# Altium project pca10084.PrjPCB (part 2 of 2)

## Sheet pca10084_sheet7_power_supply.SchDoc: PCA10084 - Power Supply
size A3; Organization: Nordic Semiconductor; DocumentNumber: 7; Revision: 0.7.0; SheetNumber: 7; SheetTotal: 8; Author: GETR; CompanyName: Nordic Semiconductor; DrawnBy: GETR
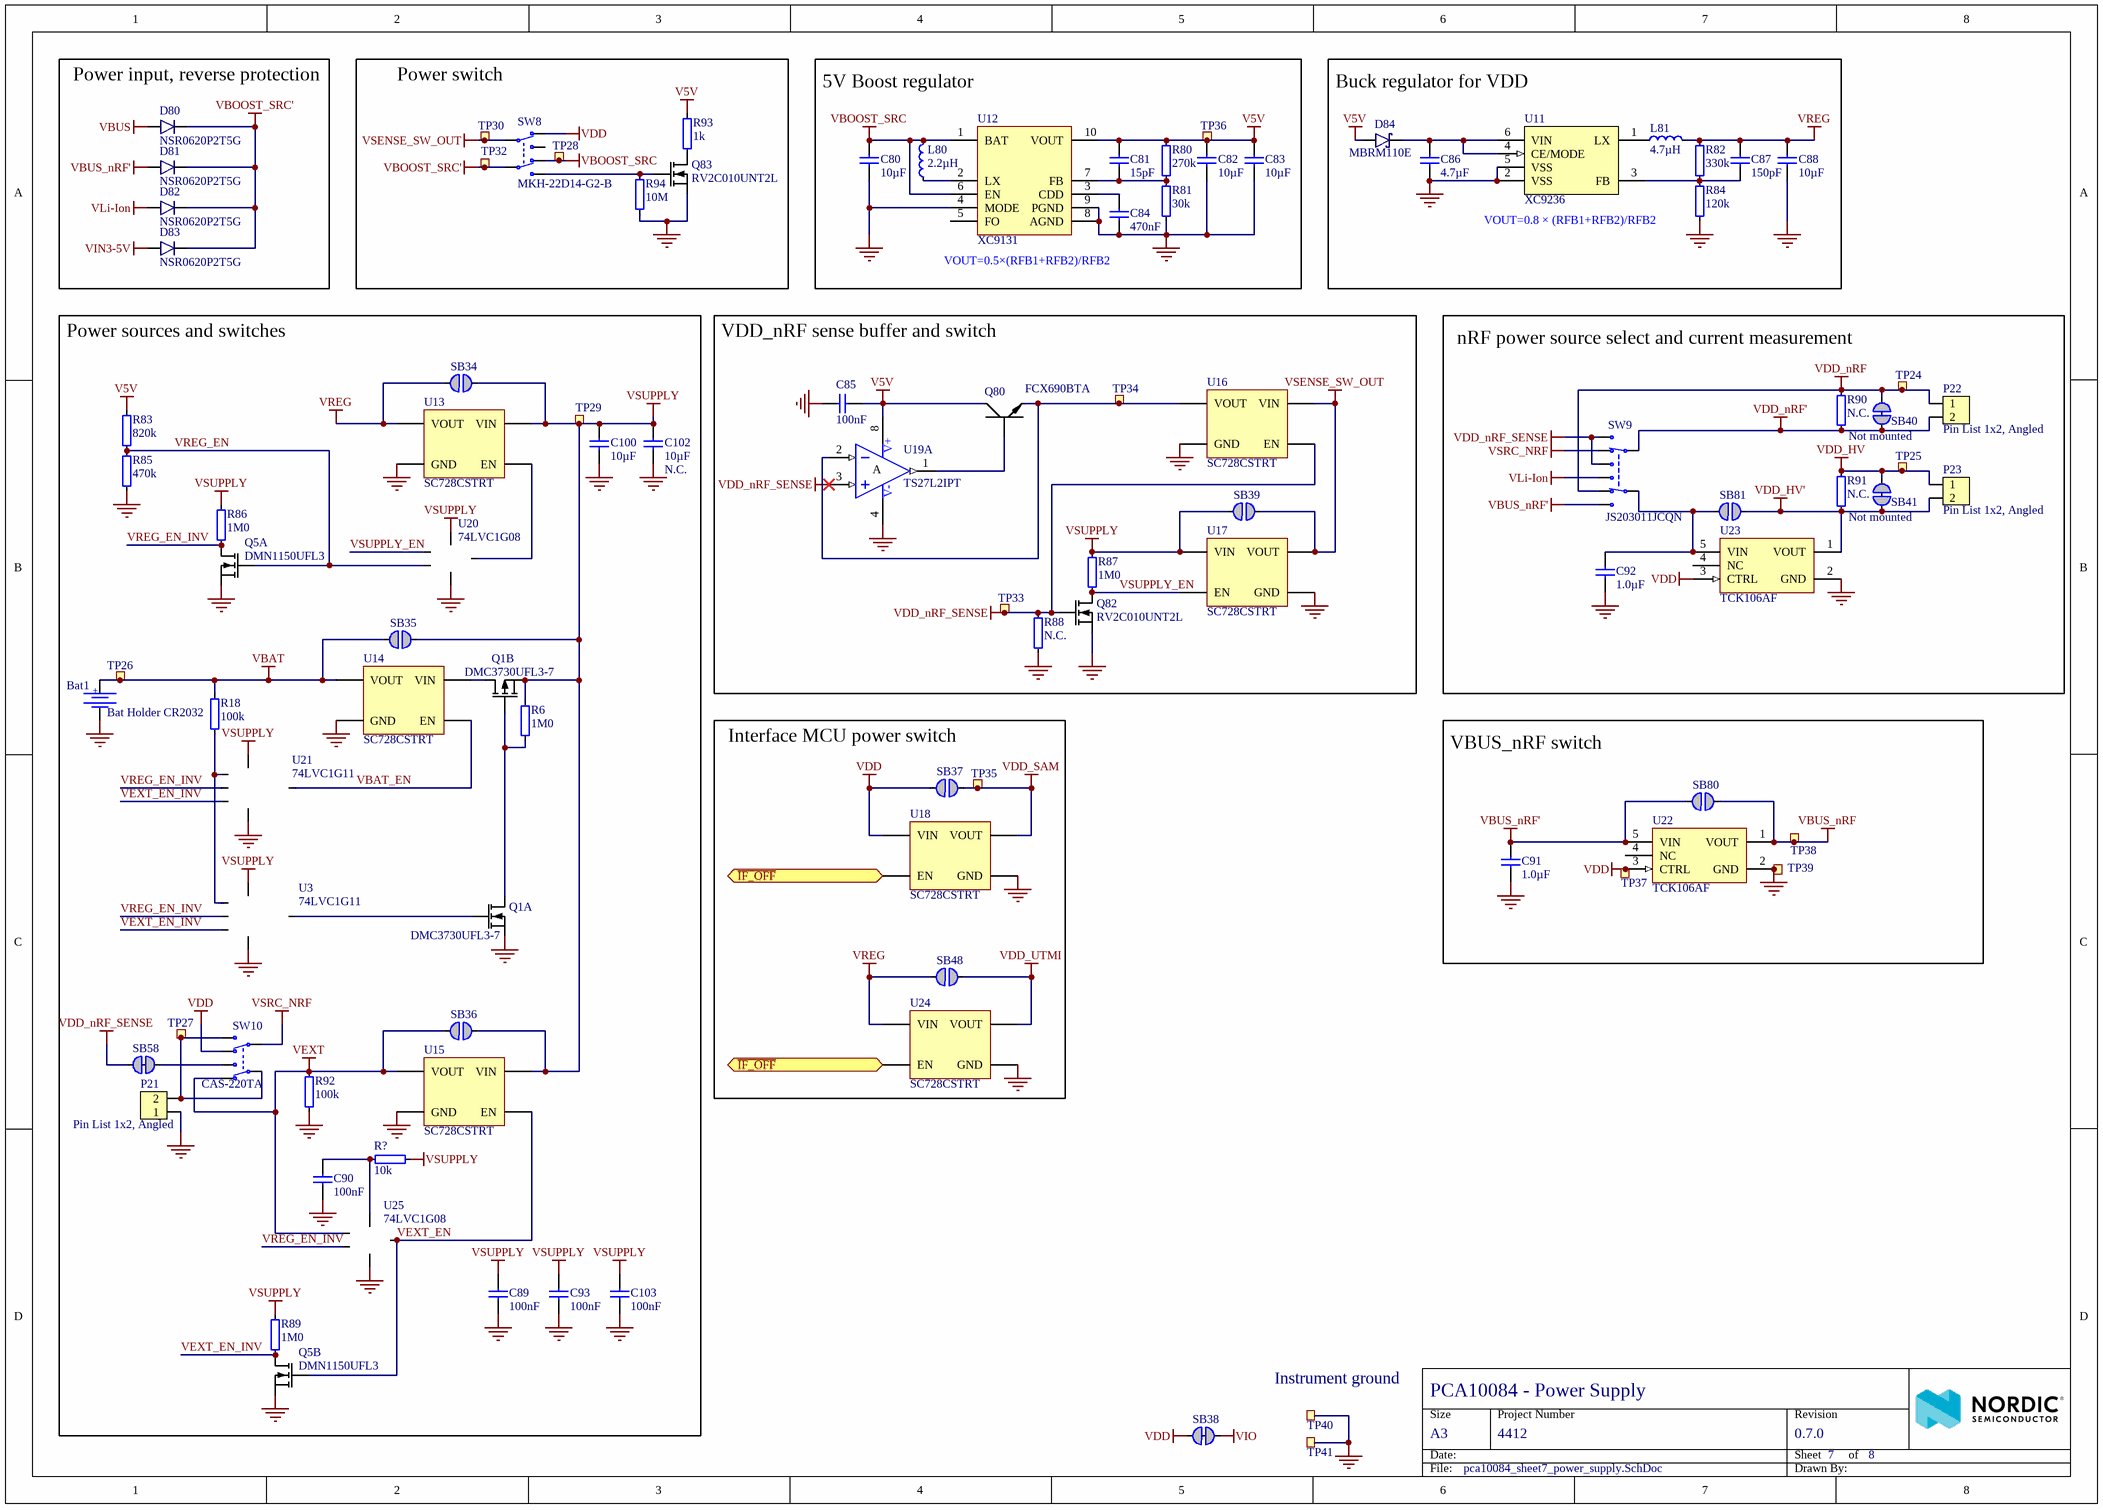
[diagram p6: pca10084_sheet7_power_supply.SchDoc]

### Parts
Bat1  Bat Holder CR2032  [CR2032_HOLDER_SMD]
C80  10µF  [CAPC1608X06L]
C81  15pF  [CAPC1005X04L]
C82  10µF  [CAPC1608X06L]
C83  10µF  [CAPC1608X06L]
C84  470nF  [CAPC1005X04L]
C85  100nF  [CAPC1005X04L]
C86  4.7µF  [CAPC2012X11L]
C87  150pF  [CAPC1005X04L]
C88  10µF  [CAPC1608X06L]
C89  100nF  [CAPC0603X03L_C]
C90  100nF  [CAPC0603X03L_C]
C91  1.0µF  [CAPC1608X06L]
C92  1.0µF  [CAPC1608X06L]
C93  100nF  [CAPC0603X03L_C]
C100  10µF  [CAPC1608X06L]
C102  10µF  Assembly: N.C.  [CAPC1608X06L]
C103  100nF  [CAPC0603X03L_C]
D80  NSR0620P2T5G  [SODFL100X40-2N]
D81  NSR0620P2T5G  [SODFL100X40-2N]
D82  NSR0620P2T5G  [SODFL100X40-2N]
D83  NSR0620P2T5G  [SODFL100X40-2N]
D84  MBRM110E  [DO-216AA]
L80  2.2µH  [TY-NR3015]
L81  4.7µH  [TY-NR3015]
P21  Pin List 1x2, Angled  [LIST_ANG_1x2-SMD-2.54MM]
P22  Pin List 1x2, Angled  [LIST_ANG_1x2-SMD-2.54MM]
P23  Pin List 1x2, Angled  [LIST_ANG_1x2-SMD-2.54MM]
Q1  DMC3730UFL3-7  [DMC3730UFL3-7]  (parts A,B of 2)
Q5  DMN1150UFL3  [X2DFN35P100X130X35-6N]  (parts A,B of 2)
Q80  FCX690BTA  [SOT89-150P409X160-3N]
Q82  RV2C010UNT2L  [DFN65P100X40-3L]
Q83  RV2C010UNT2L  [DFN65P100X40-3L]
R6  1M0  [RESC0603X03L_C]
R18  100k  [RESC0603X03L_C]
R80  270k  [RESC1005X04L]
R81  30k  [RESC1005X04L]
R82  330k  [RESC1005X04L]
R83  820k  [RESC0603X03L_C]
R84  120k  [RESC1005X04L]
R85  470k  [RESC0603X03L_C]
R86  1M0  [RESC0603X03L_C]
R87  1M0  [RESC1005X04L]
R88  N.C.  [RESC1005X04L]
R89  1M0  [RESC0603X03L_C]
R90  N.C.  Assembly: Not mounted  [RESC1005X04L]
R91  N.C.  Assembly: Not mounted  [RESC1005X04L]
R92  100k  [RESC1005X04L]
R93  1k  [RESC1005X04L]
R94  10M  [RESC1005X04L]
R?  10k  [RESC0603X03L_C]
SB34  Solderbridge  [Solderbridge]  (value not drawn)  (no BOM)
SB35  Solderbridge  [Solderbridge]  (value not drawn)  (no BOM)
SB36  Solderbridge  [Solderbridge]  (value not drawn)  (no BOM)
SB37  Solderbridge  [Solderbridge]  (value not drawn)  (no BOM)
SB38  Solderbridge  [Solderbridge_Shorted]  (value not drawn)  (net tie, no BOM)
SB39  Solderbridge  [Solderbridge]  (value not drawn)  (no BOM)
SB40  Solderbridge  [Solderbridge_Shorted]  (value not drawn)  (net tie, no BOM)
SB41  Solderbridge  [Solderbridge_Shorted]  (value not drawn)  (net tie, no BOM)
SB48  Solderbridge  [Solderbridge]  (value not drawn)  (no BOM)
SB58  Solderbridge  [Solderbridge_Shorted]  (value not drawn)  (net tie, no BOM)
SB80  Solderbridge  [Solderbridge]  (value not drawn)  (no BOM)
SB81  Solderbridge  [Solderbridge]  (value not drawn)  (no BOM)
SW8  MKH-22D14-G2-B  [MKH-22D14-G2-B]
SW9  JS203011JCQN  [Switch-Slide-J-Lead-DP3T-13x3.5mm]
SW10  CAS-220TA  [CAS-220TA]
TP24  Ø1.0mm,SMD  [TP_SMD_Ø1.0mm]  (value not drawn)  (no BOM)
TP25  Ø1.0mm,SMD  [TP_SMD_Ø1.0mm]  (value not drawn)  (no BOM)
TP26  Ø1.0mm,SMD  [TP_SMD_Ø1.0mm]  (value not drawn)  (no BOM)
TP27  Ø1.0mm,SMD  [TP_SMD_Ø1.0mm]  (value not drawn)  (no BOM)
TP28  Ø1.0mm,SMD  [TP_SMD_Ø1.0mm]  (value not drawn)  (no BOM)
TP29  Ø1.0mm,SMD  [TP_SMD_Ø1.0mm]  (value not drawn)  (no BOM)
TP30  Ø1.0mm,SMD  [TP_SMD_Ø1.0mm]  (value not drawn)  (no BOM)
TP32  Ø1.0mm,SMD  [TP_SMD_Ø1.0mm]  (value not drawn)  (no BOM)
TP33  Ø1.0mm,SMD  [TP_SMD_Ø1.0mm]  (value not drawn)  (no BOM)
TP34  Ø1.0mm,SMD  [TP_SMD_Ø1.0mm]  (value not drawn)  (no BOM)
TP35  Ø1.0mm,SMD  [TP_SMD_Ø1.0mm]  (value not drawn)  (no BOM)
TP36  Ø1.0mm,SMD  [TP_SMD_Ø1.0mm]  (value not drawn)  (no BOM)
TP37  Ø1.0mm,SMD  [TP_SMD_Ø1.0mm]  (value not drawn)  (no BOM)
TP38  Ø1.0mm,SMD  [TP_SMD_Ø1.0mm]  (value not drawn)  (no BOM)
TP39  Ø1.0mm,SMD  [TP_SMD_Ø1.0mm]  (value not drawn)  (no BOM)
TP40  TP  [TESTPAD-TH]  (value not drawn)  (no BOM)
TP41  TP  [TESTPAD-TH]  (value not drawn)  (no BOM)
U3  74LVC1G11  [SOT65P210X100-6N]
U11  XC9236  [USP-6C]
U12  XC9131  [10-USPB (2.9x2.6)]
U13  SC728CSTRT  [BGA4C40P2X2_76X76X62]
U14  SC728CSTRT  [BGA4C40P2X2_76X76X62]
U15  SC728CSTRT  [BGA4C40P2X2_76X76X62]
U16  SC728CSTRT  [BGA4C40P2X2_76X76X62]
U17  SC728CSTRT  [BGA4C40P2X2_76X76X62]
U18  SC728CSTRT  [BGA4C40P2X2_76X76X62]
U19  TS27L2IPT  [TSOP65P640X120-8N]  (part A of 2)
U20  74LVC1G08  [SOT65P210X100-5N]
U21  74LVC1G11  [SOT65P210X100-6N]
U22  TCK106AF  [SOT95P280X140-5N]
U23  TCK106AF  [SOT95P280X140-5N]
U24  SC728CSTRT  [BGA4C40P2X2_76X76X62]
U25  74LVC1G08  [SOT65P210X100-5N]

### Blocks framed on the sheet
Power input, reverse protection: D80-D83
Power switch: Q83 R93 R94 SW8 TP28 TP30 TP32
5V Boost regulator: C80-C84 L80 R80 R81 TP36 U12
Buck regulator for VDD: C86-C88 D84 L81 R82 R84 U11
Power sources and switches: Bat1 C89 C90 C93 C100 C102 C103 P21 Q1 Q5 R6 R18 R83 R85 R86 R89 R92 R? SB34-SB36 SB58 SW10 TP26 TP27 TP29 U3 U13-U15 U20 U21 U25
VDD_nRF sense buffer and switch: C85 Q80 Q82 R87 R88 SB39 TP33 TP34 U16 U17 U19
nRF power source select and current measurement: C92 P22 P23 R90 R91 SB40 SB41 SB81 SW9 TP24 TP25 U23
Interface MCU power switch: SB37 SB48 TP35 U18 U24
VBUS_nRF switch: C91 SB80 TP37-TP39 U22

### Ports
~{IF_OFF} (bidir)

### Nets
GND: Bat1.2 C80.1 C82.1 C83.1 C84.1 C85.1 C86.1 C88.1 C89.1 C90.1 C91.1 C92.1 C93.1 C100.1 C102.1 C103.1 P21.1 Q1.1(S1) Q5.1(S1) Q5.4(S2) Q82.2(S) Q83.2(S) R81.1 R84.1 R85.2 R88.2 R92.2 R94.2 TP39.1 TP40.1 TP41.1 U3.2(GND) U11.2(VSS) U11.5(VSS) U11.7(VSS) U12.4(MODE) U12.8(AGND) U12.9(PGND) U12.11(GND) U13.B1(GND) U14.B1(GND) U15.B1(GND) U16.B1(GND) U17.B1(GND) U18.B1(GND) U19.4(V-) U20.3(GND) U21.2(GND) U22.2(GND) U23.2(GND) U24.B1(GND) U25.3(GND)
V5V: C81.2 C82.2 C83.2 C85.2 D84.1(A) Q80.2(C) R80.2 R83.1 R93.1 TP36.1 U12.10(VOUT) U19.8(V+)
VBAT: Bat1.1 R18.1 SB35.2 TP26.1 U14.A1(VOUT)
VBOOST_SRC: C80.2 L80.2 SW8.6(N.C-2) TP28.1 U12.1(BAT) U12.6(EN)
VBOOST_SRC': D80.1(C) D81.1(C) D82.1(C) D83.1(C) SW8.5(COM-2) TP32.1
VBUS: D80.2(A)
VBUS_nRF: SB80.1 TP38.1 U22.1(VOUT)
VBUS_nRF': C91.2 D81.2(A) SB80.2 SW9.8(N.O) U22.5(VIN)
VDD: SB37.2 SB38.2 SW8.3(N.C-1) SW10.6(N.C-2) TP37.1 U18.A2(VIN) U22.3(CTRL) U23.3(CTRL)
VDD_HV: P23.1 R91.2 SB41.1 TP25.1
VDD_HV': P23.2 R91.1 SB41.2 SB81.1 U23.1(VOUT)
VDD_nRF: P22.1 R90.2 SB40.1 SW9.6(N.C) TP24.1
VDD_nRF': P22.2 R90.1 SB40.2 SW9.3(COM)
VDD_nRF_SENSE: Q82.1(G) R88.1 SB58.1 SW9.1(N.O) SW9.4(N.O) TP33.1 U16.B2(EN) U19.3(IN1+)
VDD_SAM: SB37.1 TP35.1 U18.A1(VOUT)
VDD_UTMI: SB48.1 U24.A1(VOUT)
VEXT: R92.1 SB36.2 SW10.3(N.C-1) U15.A1(VOUT) U25.1(A)
VIN3-5V: D83.2(A)
VIO: SB38.1
VLi-Ion: D82.2(A) SW9.5(N.O)
VREG: C87.2 C88.2 L81.2 R82.2 SB34.2 SB48.2 U13.A1(VOUT) U24.A2(VIN)
VSENSE_SW_OUT: SB39.1 SW8.2(COM-1) TP30.1 U16.A2(VIN) U17.A1(VOUT)
VSRC_NRF: SW9.2(N.C) SW10.5(COM-2)
VSUPPLY: C89.2 C93.2 C100.2 C102.2 C103.2 Q1.4(S2) R6.1 R86.1 R87.1 R89.1 R?.1 SB34.1 SB35.1 SB36.1 SB39.2 TP29.1 U3.5(VCC) U13.A2(VIN) U15.A2(VIN) U17.A2(VIN) U20.5(VCC) U21.5(VCC)
~{IF_OFF}: U18.B2(EN) U24.B2(EN) ; port ~{IF_OFF}
VBAT_EN: U14.B2(EN) U21.4(Y)
VEXT_EN: Q5.5(G2) U15.B2(EN) U25.4(Y)
VEXT_EN_INV: Q5.3(D2) R89.2 U3.6(C) U21.6(C)
VREG_EN: Q5.2(G1) R83.2 R85.1 U20.2(B)
VREG_EN_INV: Q5.6(D1) R86.2 U3.3(B) U21.3(B) U25.2(B)
VSUPPLY_EN: Q82.3(D) R87.2 U17.B2(EN) U20.1(A)
NetC81_1: C81.1 R80.1 R81.2 U12.7(FB)
NetC84_2: C84.2 U12.3(CDD)
NetC86_2: C86.2 D84.3(C) U11.4(CE/MODE) U11.6(VIN)
NetC87_1: C87.1 R82.1 R84.2 U11.3(FB)
NetC90_2: C90.2 R?.2 U25.5(VCC)
NetC92_2: C92.2 SB81.2 SW9.7(COM) U23.5(VIN)
NetL80_1: L80.1 U12.2(LX)
NetL81_1: L81.1 U11.1(LX)
NetP21_2: P21.2 SW10.2(COM-1) SW10.4(N.O-2) TP27.1
NetQ1_2: Q1.2(G1) U3.4(Y)
NetQ1_3: Q1.3(D2) U14.A2(VIN)
NetQ1_5: Q1.5(G2) Q1.6(D1) R6.2
NetQ80_1: Q80.1(B) U19.1(OUT1)
NetQ80_3: Q80.3(E) TP34.1 U16.A1(VOUT) U19.2(IN1-)
NetQ83_1: Q83.1(G) R94.1 SW8.4(N.O-2)
NetQ83_3: Q83.3(D) R93.2
NetR18_2: R18.2 U3.1(A) U21.1(A)
NetSB58_2: SB58.2 SW10.1(N.O-1)
NetU13_B2: U13.B2(EN) U20.4(Y)

Not connected (* = marked no-connect by the designer): SW8 1(N.O-1); U12 5(FO); U22 4(NC); U23 4(NC)

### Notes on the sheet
- VOUT=0.8 × (RFB1+RFB2)/RFB2
- VOUT=0.5×(RFB1+RFB2)/RFB2
- (near TP40) Instrument ground

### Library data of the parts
Bat1 = Bat Holder CR2032 SMD: Manufacturer: Comfortable; Manufacturer Part Number: BC-2001; Part number IPS: N.A.; Artikkelnr Noca: 55089011
C80 C82 C83 C88 = C0603-10µF-25V: Capacitor, 0603, 25V, X5R; Part number IPS: N.A.; Artikkelnr Noca: 20039436
C81 = C0402-15p: Capacitor, NP0, ±5%; Part number IPS: 00000002401; Note: 50V; Artikkelnr Noca: 20029141
C84 = C0402-470n: Capacitor, X5R, ±10%; Part number IPS: N.A.; Note: 6.3V; Artikkelnr Noca: 20039350
C85 = C0402-100n: Capacitor, X7R, ±10%; Part number IPS: 00000005296; Note: 16V; Artikkelnr Noca: 20039200
C86 = C0805-4µ7: Capacitor, X5R, ±10%; Part number IPS: N.A.; Note: 16V; Artikkelnr Noca: 20039266
C87 = C0402-150p: Capacitor, NP0, ±5%; Part number IPS: 00000007972; Note: 50V; Artikkelnr Noca: 20029111
C89 C90 C93 C103 = C0201-100n: Capacitor, X5R, ±10%; Part number IPS: 00000001248; Note: 16V; Artikkelnr Noca: N.A.
C91 C92 = C0603-1µ0: Capacitor, X7R, ±10%; Part number IPS: 00000000616; Note: 16V; Artikkelnr Noca: 20039282
C100 C102 = C0603-10µ-6.3V: CAP CER 10UF 6.3V X7R 0603; Artikkelnr Noca: N.A.
D80-D83 = NSR0620P2T5G: 20V schottky barrier diode, Vf 350 mV @ 100 mA, Ir 2.0 µA @ 10 V, If 500 mA; Manufacturer: ON Semiconductor; Part number IPS: N.A.; Artikkelnr Noca: 10029169
D84 = MBRM110E: Diode Schottky Vf=0.455V @ 100mA, Vr=10V, If=1000mA, Ir=1µA @ 10V; Manufacturer: ON Semiconductor; Manufacturer Part Number: MBRM110ET1G; Part number IPS: N.A.; Artikkelnr Noca: 10029172
L80 = NR3015-2µ2-1.5A-72mOhm: Ferrite Inductor, Shielded, 1,5A, 72mOhm; Manufacturer: Taiyo Yuden; Manufacturer Part Number: NR3015T2R2M; Part number IPS: N.A.; Artikkelnr Noca: 33029487
L81 = NR3015-4µ7-1.04A-144mOhm: Ferrite Inductor, Shielded, 1,04A, 144mOhm; Manufacturer: Taiyo Yuden; Manufacturer Part Number: NR3015T4R7M; Part number IPS: N.A.; Artikkelnr Noca: 33029551
P21-P23 = Pin List Ang 1x2 SMD, 2.54mm: Pin List 1x2, 2.54mm (100mil), Right Angled, SMD; Manufacturer: W-CON; Manufacturer Part Number: 1125B-1102S0Z135R2; Part number IPS: N.A.; Artikkelnr Noca: 55010023
Q1 = DMC3730UFL3-7: MOSFET N/P-CHA 30V 1.1A DFN1310; Manufacturer: Diodes Incorporated; Artikkelnr Noca: N.A.
Q5 = DMN1150UFL3: Dual N-Channel FET; Manufacturer: Diodes Incorporated; Artikkelnr Noca: N.A.
Q80 = FCX690BTA: 45V NPN high gain power transistor; Manufacturer: Diodes Incorporated; Part number IPS: N.A.; Artikkelnr Noca: 35010019
Q82 Q83 = RV2C010UNT2L: N-Channel MOSFET, 20V, 1A, 470mOhm, 400mW; Manufacturer: Rohm Semiconductor; Part number IPS: N.A.; Artikkelnr Noca: 35010020
R6 R86 R89 = R0201-1M0: Resistor, ±1%, 0.05W; Note: Chip Res 1%; Artikkelnr Noca: N.A.
R18 = R0201-100k: Resistor, ±1%, 0.05W; Note: Chip Res 1%; Artikkelnr Noca: N.A.
R80 = R0402-270k: Resistor, ±1%, 0.063W; Part number IPS: N.A.; Note: Chip Res 1%; Artikkelnr Noca: 27049131
R81 = R0402-30k: Resistor, ±1%, 0.063W; Part number IPS: N.A.; Note: Chip Res 1%; Artikkelnr Noca: 27049108
R82 = R0402-330k: Resistor, ±1%, 0.063W; Part number IPS: N.A.; Note: Chip Res 1%; Artikkelnr Noca: 27049133
R83 = R0201-820k: Resistor, ±1%, 0.05W; Note: Chip Res 1%; Artikkelnr Noca: N.A.
R84 = R0402-120k: Resistor, ±1%, 0.063W; Part number IPS: N.A.; Note: Chip Res 1%; Artikkelnr Noca: 27049123
R85 = R0201-470k: Resistor, ±1%, 0.05W; Note: Chip Res 1%; Artikkelnr Noca: N.A.
R87 = R0402-1M0: Resistor, ±1%, 0.063W; Part number IPS: 00000006807; Note: Chip Res 1%; Artikkelnr Noca: 27049145
R88 = R0402-N.C.: Not mounted; Note: Chip Res; Artikkelnr Noca: N.A.; Assembly: Not mounted
R90 R91 = R0402-N.C.: Not mounted; Note: Chip Res; Artikkelnr Noca: N.A.
R92 = R0402-100k: Resistor, ±1%, 0.063W; Part number IPS: 00000003667; Note: Chip Res 1%; Artikkelnr Noca: 27049121
R93 = R0402-1k0: Resistor, ±1%, 0.063W; Part number IPS: 00000002218; Note: Chip Res 1%; Artikkelnr Noca: 27049073
R94 = R0402-10M: Resistor, ±1%, 0.063W; Part number IPS: N.A.; Note: Chip Res 1%; Artikkelnr Noca: 27049169
R? = R0201-10k: Resistor, ±1%, 0.05W; Part number IPS: 00000001255; Note: Chip Res 1%; Artikkelnr Noca: N.A.
SB34-SB37 SB39 SB48 SB80 SB81 = Solderbridge: Artikkelnr Noca: N.A.
SB38 SB40 SB41 SB58 = Solderbridge Shorted: Shorted Solderbridge; Artikkelnr Noca: N.A.
SW8 = MKH-22D14-G2-B: Slide Switch DPDT; Manufacturer: Dailywell; Part number IPS: N.A.; Artikkelnr Noca: 50019112
SW9 = JS203011JCQN: Slide Switch DP3T 300mA 6V; Manufacturer: C&K Components; Part number IPS: N.A.; Artikkelnr Noca: 50019116
SW10 = CAS-220TA: Slide Switch DPDT J Hook; Manufacturer: Copal Electronics Inc; Part number IPS: N.A.; Artikkelnr Noca: 50019042
TP24-TP30 TP32-TP39 = TP_SMD_Ø1.0MM: 1.0mm circular SMD testpad; Manufacturer: Nordic Semiconductor; Artikkelnr Noca: N.A.
TP40 TP41 = Testpoint TH: Testpoint, through hole; Artikkelnr Noca: N.A.
U3 U21 = 74LVC1G11GW: Single 3-input AND gate; Manufacturer: NXP Semiconductors; Part number IPS: N.A.; Artikkelnr Noca: 15079348
U11 = XC9236D08CER-G: 600mA Driver Transistor Built-In, Synchronous Step-Down DC/DC Converters; Manufacturer: Torex Semiconductor; Part number IPS: N.A.; Artikkelnr Noca: 17030085
U12 = XC9131H05CDR-G: 1A Driver Transistor Built-In, Multi Functional Step-Up DC/DC Converter; Manufacturer: Torex Semiconductor; Part number IPS: N.A.; Artikkelnr Noca: 17030086
U13-U18 U24 = SC728CSTRT: Semtech, 2A Low Vin, Very Low Ron, Load Switch, 4DSBGA; Manufacturer: Semtech Corporation; Part number IPS: N.A.; Artikkelnr Noca: 15070081
U19 = TS27L2IPT: Precision very low power CMOS dual operational amplifier; Manufacturer: STMicroelectronics; Part number IPS: N.A.; Artikkelnr Noca: 17010019
U20 U25 = 74LVC1G08GW: Single 2-Input AND Gate; Manufacturer: NXP Semiconductors; Part number IPS: N.A.; Artikkelnr Noca: 15049058
U22 U23 = TCK106AF,LF: 1.0 A Load Switch IC with Slew Rate Control Driver in Small Package; Manufacturer: Toshiba; Part number IPS: 00000007823; Artikkelnr Noca: 15070086

## Sheet pca10084_sheet8_skyworks.SchDoc: PCA20035 - FEM
size A3; Organization: Nordic Semiconductor; DocumentNumber: 8; Revision: 0.7.0; SheetNumber: 8; SheetTotal: 8; Author: GETR; CompanyName: Nordic Semiconductor; DrawnBy: GETR
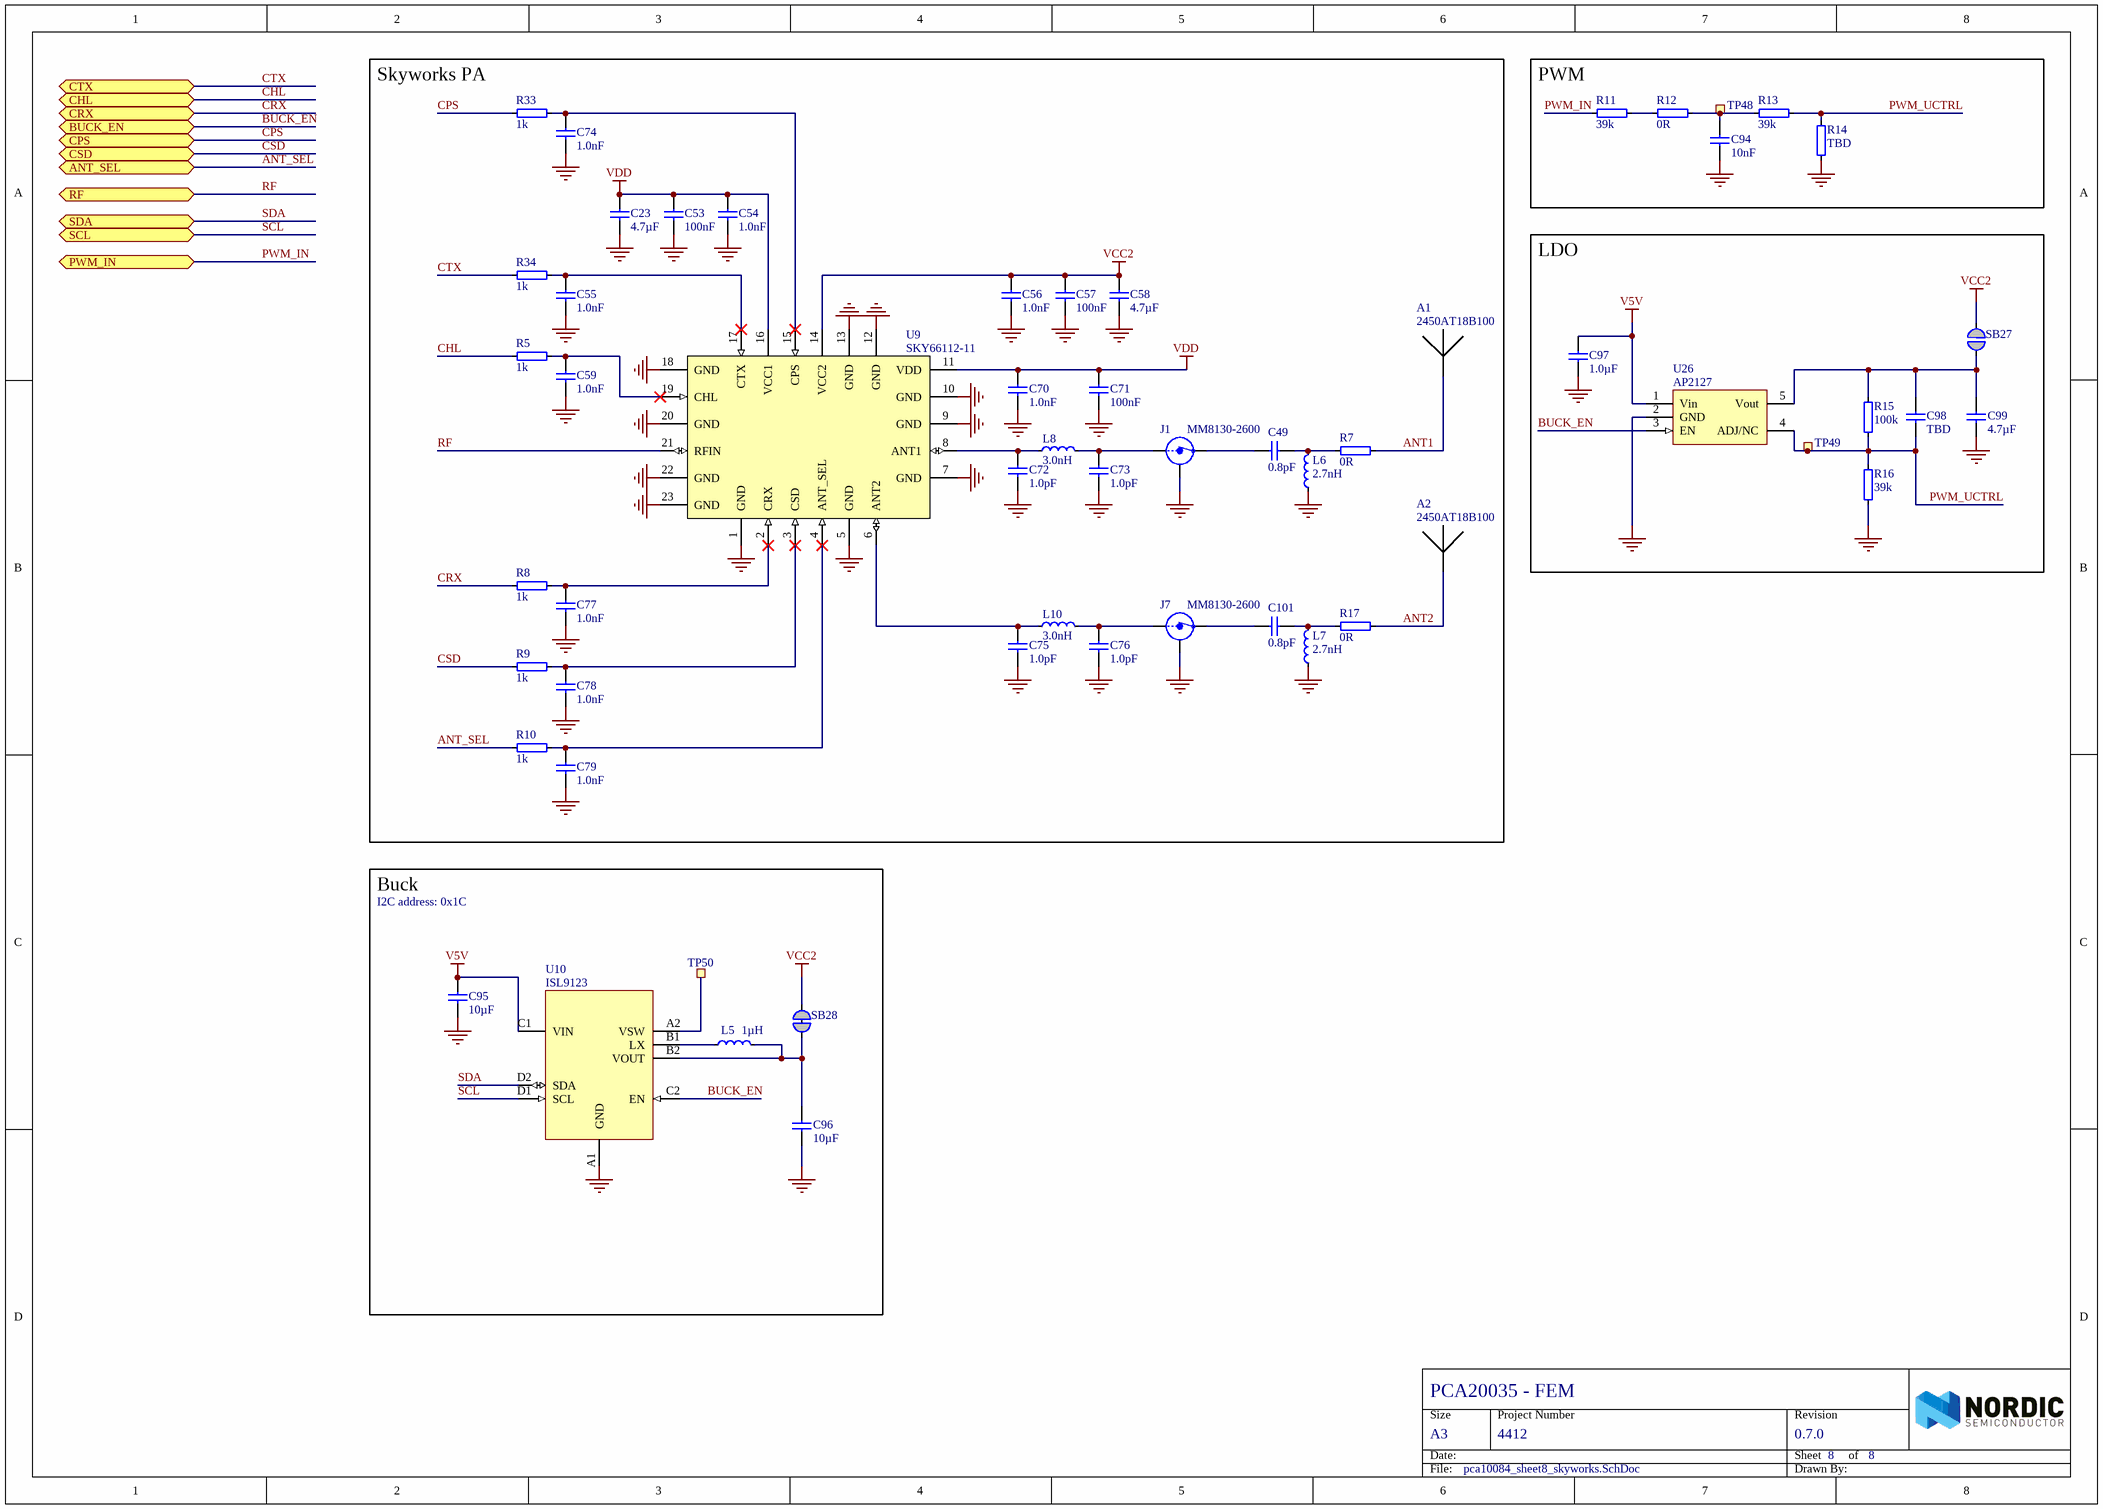
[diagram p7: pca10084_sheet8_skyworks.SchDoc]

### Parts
A1  2450AT18B100  [2450AT18B100]
A2  2450AT18B100  [2450AT18B100]
C23  4.7µF  [CAPC1005X04L]
C49  0.8pF  [CAPC1005X04L]
C53  100nF  [CAPC1005X04L]
C54  1.0nF  [CAPC1005X04L]
C55  1.0nF  [CAPC1005X04L]
C56  1.0nF  [CAPC1005X04L]
C57  100nF  [CAPC1005X04L]
C58  4.7µF  [CAPC1005X04L]
C59  1.0nF  [CAPC1005X04L]
C70  1.0nF  [CAPC1005X04L]
C71  100nF  [CAPC1005X04L]
C72  1.0pF  [CAPC1005X04L]
C73  1.0pF  [CAPC1005X04L]
C74  1.0nF  [CAPC1005X04L]
C75  1.0pF  [CAPC1005X04L]
C76  1.0pF  [CAPC1005X04L]
C77  1.0nF  [CAPC1005X04L]
C78  1.0nF  [CAPC1005X04L]
C79  1.0nF  [CAPC1005X04L]
C94  10nF  [CAPC1005X04L]
C95  10µF  [CAPC1608X06L]
C96  10µF  [CAPC1608X06L]
C97  1.0µF  [CAPC1005X04L]
C98  TBD  [CAPC1005X04L]
C99  4.7µF  [CAPC1005X04L]
C101  0.8pF  [CAPC1005X04L]
J1  MM8130-2600  [COAXIAL-SWF]
J7  MM8130-2600  [COAXIAL-SWF]
L5  1µH  [INDC1608X06L]
L6  2.7nH  [INDC1005X04L]
L7  2.7nH  [INDC1005X04L]
L8  3.0nH  [INDC1005X04L]
L10  3.0nH  [INDC1005X04L]
R5  1k  [RESC1005X04L]
R7  0R  [RESC1005X04L]
R8  1k  [RESC1005X04L]
R9  1k  [RESC1005X04L]
R10  1k  [RESC1005X04L]
R11  39k  [RESC1005X04L]
R12  0R  [RESC3216X08N]
R13  39k  [RESC1005X04L]
R14  TBD  [RESC1005X04L]
R15  100k  [RESC1005X04L]
R16  39k  [RESC1005X04L]
R17  0R  [RESC1005X04L]
R33  1k  [RESC1005X04L]
R34  1k  [RESC1005X04L]
SB27  Solderbridge  [Solderbridge]  (value not drawn)  (no BOM)
SB28  Solderbridge  [Solderbridge_Shorted]  (value not drawn)  (net tie, no BOM)
TP48  Ø1.0mm,SMD  [TP_SMD_Ø1.0mm]  (value not drawn)  (no BOM)
TP49  Ø1.0mm,SMD  [TP_SMD_Ø1.0mm]  (value not drawn)  (no BOM)
TP50  Ø1.0mm,SMD  [TP_SMD_Ø1.0mm]  (value not drawn)  (no BOM)
U9  SKY66112-11  [SKY66112-11]
U10  ISL9123  [BGA8C40P2X4_100X180X55]
U26  AP2127  [SOT95P282X145-5N]

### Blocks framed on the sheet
Skyworks PA: A1 A2 C23 C49 C53-C59 C70-C79 C101 J1 J7 L6-L8 L10 R5 R7-R10 R17 R33 R34 U9
PWM: C94 R11-R14 TP48
LDO: C97-C99 R15 R16 SB27 TP49 U26
Buck: C95 C96 L5 SB28 TP50 U10

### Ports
ANT_SEL (bidir), BUCK_EN (bidir), CHL (bidir), CPS (bidir), CRX (bidir), CSD (bidir), CTX (bidir), PWM_IN (bidir), RF (bidir), SCL (bidir), SDA (bidir)

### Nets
GND: C23.1 C53.1 C54.1 C55.1 C56.1 C57.1 C58.1 C59.1 C70.1 C71.1 C72.1 C73.1 C74.1 C75.1 C76.1 C77.1 C78.1 C79.1 C94.1 C95.1 C96.1 C97.1 C99.1 J1.2(Shield) J7.2(Shield) L6.1 L7.1 R14.1 R16.1 U9.1(GND) U9.5(GND) U9.7(GND) U9.9(GND) U9.10(GND) U9.12(GND) U9.13(GND) U9.18(GND) U9.20(GND) U9.22(GND) U9.23(GND) U10.A1(GND) U26.2(GND)
V5V: C95.2 C97.2 U10.C1(VIN) U26.1(Vin)
VCC2: C56.2 C57.2 C58.2 SB27.1 SB28.1 U9.14(VCC2)
VDD: C23.2 C53.2 C54.2 C70.2 C71.2 U9.11(VDD) U9.16(VCC1)
ANT1: A1.1 R7.1
ANT2: A2.1 R17.1
ANT_SEL: R10.1 ; port ANT_SEL
BUCK_EN: U10.C2(EN) U26.3(EN) ; port BUCK_EN
CHL: R5.1 ; port CHL
CPS: R33.1 ; port CPS
CRX: R8.1 ; port CRX
CSD: R9.1 ; port CSD
CTX: R34.1 ; port CTX
PWM_IN: R11.1 ; port PWM_IN
PWM_UCTRL: C98.1 R13.1 R14.2 R15.1 R16.2 TP49.1 U26.4(ADJ/NC)
RF: U9.21(RFIN) ; port RF
SCL: U10.D1(SCL) ; port SCL
SDA: U10.D2(SDA) ; port SDA
NetC49_1: C49.1 L6.2 R7.2
NetC49_2: C49.2 J1.3(OUT)
NetC55_2: C55.2 R34.2 U9.17(CTX)
NetC59_2: C59.2 R5.2 U9.19(CHL)
NetC72_2: C72.2 L8.1 U9.8(ANT1)
NetC73_2: C73.2 J1.1(IN) L8.2
NetC74_2: C74.2 R33.2 U9.15(CPS)
NetC75_2: C75.2 L10.1 U9.6(ANT2)
NetC76_2: C76.2 J7.1(IN) L10.2
NetC77_2: C77.2 R8.2 U9.2(CRX)
NetC78_2: C78.2 R9.2 U9.3(CSD)
NetC79_2: C79.2 R10.2 U9.4(ANT_SEL)
NetC94_2: C94.2 R12.2 R13.2 TP48.1
NetC96_2: C96.2 L5.2 SB28.2 U10.B2(VOUT)
NetC98_2: C98.2 C99.2 R15.2 SB27.2 U26.5(Vout)
NetC101_1: C101.1 L7.2 R17.2
NetC101_2: C101.2 J7.3(OUT)
NetL5_1: L5.1 U10.B1(LX)
NetR11_2: R11.2 R12.1
NetTP50_1: TP50.1 U10.A2(VSW)

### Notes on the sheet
- I2C address: 0x1C

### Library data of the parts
A1 A2 = Johanson 2450AT18B100: 2.45 GHz chip antenna; Manufacturer: Johanson Technology; Part number IPS: 00000007781; Artikkelnr Noca: N.A.
C23 C58 C99 = C0402-4µ7: Capacitor, X5R, ±20%; Part number IPS: 00000001251; Note: 10V; Artikkelnr Noca: 20039482
C49 C101 = C0402-0.8p: Capacitor, NP0, ±5%; Part number IPS: 00000007782; Note: 50V; Artikkelnr Noca: 20029147
C53 C57 C71 = C0402-100n: as C85 on sheet pca10084_sheet7_power_supply
C54-C56 C59 C70 C74 C77-C79 = C0402-1n0: Capacitor, X7R, ±10%; Part number IPS: N.A.; Note: 50V; Artikkelnr Noca: 20039223
C72 C73 C75 C76 = C0402-1.0p: Capacitor, NP0, ±0.1pF; Part number IPS: N.A.; Note: 50V; Artikkelnr Noca: 20029140
C94 = C0402-10n: Capacitor, X7R, ±10%; Part number IPS: 00000007784; Note: 16V; Artikkelnr Noca: 20039166
C95 C96 = C0603-10µ: Capacitor, X5R, ±20%; Part number IPS: 00000007785; Note: 6.3V; Artikkelnr Noca: 20039234
C97 = C0402-1µ0: Capacitor, X5R, ±5%; Part number IPS: 00000007786; Note: 6.3V; Artikkelnr Noca: 20039235
C98 = C0402-TBD: Chip Cap 0402; Artikkelnr Noca: N.A.
J1 J7 = MM8130-2600: Coaxial Connector with Switch; Manufacturer: Murata; Part number IPS: N.A.; Artikkelnr Noca: 55029011
L5 = L0603-1µH: FIXED IND 1UH 1A 200 MOHM SMD; Manufacturer: Abracon Corporation; Manufacturer Part Number: ASMPH-0603-1R0M-T; Part number IPS: N:A; Artikkelnr Noca: N.A.
L6 L7 = L0402-2n7-HT: THIN FILM 2.7NH ±0.1nH 0402; Manufacturer: Wurth Elektronik; Manufacturer Part Number: 744901027; Note: -40°C ~ 125°C; Artikkelnr Noca: N.A.
L8 L10 = L0402-3n0: FIXED IND 3NH 800MA 200 MOHM SMD; Manufacturer: TDK Corporation; Manufacturer Part Number: MLG1005S3N0BT000; Note: High frequency chip inductor ±5%; Artikkelnr Noca: N.A.
R5 R8-R10 R33 R34 = R0402-1k0: as R93 on sheet pca10084_sheet7_power_supply
R7 R17 = R0402-0R: Resistor, ±5%, 0.063W; Part number IPS: N.A.; Note: Chip Res 5%; Artikkelnr Noca: 27049000
R11 R13 R16 = R0402-39k: Resistor, ±1%, 0.063W; Part number IPS: N.A.; Note: Chip Res 1%; Artikkelnr Noca: 27049111
R12 = R1206-0R: RES SMD 0R 1% 1206; Note: Chip Res; Artikkelnr Noca: N.A.
R14 = R0402-TBD: Chip Res 0402; Artikkelnr Noca: N.A.
R15 = R0402-100k: as R92 on sheet pca10084_sheet7_power_supply
SB27 = Solderbridge: Artikkelnr Noca: N.A.
SB28 = Solderbridge Shorted: as SB38 on sheet pca10084_sheet7_power_supply
TP48-TP50 = TP_SMD_Ø1.0MM: as TP24-TP30 on sheet pca10084_sheet7_power_supply
U9 = SKY66112-11: 2.4 GHz ZigBee®/Thread/Bluetooth® Smart Front-End Module; Manufacturer: Skyworks; Artikkelnr Noca: N.A.
U10 = ISL9123IINZ: Ultra-Low IQ Buck Regulator with Bypass; Manufacturer: Intersil; Artikkelnr Noca: N.A.
U26 = AP2127K-ADJTRG1: IC REG LDO ADJ 0.3A SOT23-5; Manufacturer: Diodes Incorporated; Artikkelnr Noca: N.A.

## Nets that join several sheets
GND: pca10084_sheet2_nrf52840_mcu (27 pins), pca10084_sheet3_pin_map (C51.1 C52.2), pca10084_sheet4_interface_mcu (37 pins), pca10084_sheet5_misc (22 pins), pca10084_sheet6_connectors (85 pins), pca10084_sheet7_power_supply (52 pins), pca10084_sheet8_skyworks (42 pins)
V5V: pca10084_sheet6_connectors (5 pins), pca10084_sheet7_power_supply (12 pins), pca10084_sheet8_skyworks (C95.2 C97.2 U10.C1 U26.1)
VBUS: pca10084_sheet5_misc (Q4.2 R40.1), pca10084_sheet6_connectors (C69.2 FB61.2 J4.5), pca10084_sheet7_power_supply (D80.2)
VBUS_nRF: pca10084_sheet2_nrf52840_mcu (C21.1 U1.AD2), pca10084_sheet7_power_supply (SB80.1 TP38.1 U22.1)
VBUS_nRF': pca10084_sheet6_connectors (C68.2 FB60.2), pca10084_sheet7_power_supply (5 pins)
VDD: pca10084_sheet5_misc (18 pins), pca10084_sheet6_connectors (R68.2 SB47.1 SB59.2), pca10084_sheet7_power_supply (8 pins), pca10084_sheet8_skyworks (7 pins)
VDD_HV: pca10084_sheet2_nrf52840_mcu (C19.1 U1.Y2), pca10084_sheet6_connectors (P20.10 P26.10), pca10084_sheet7_power_supply (P23.1 R91.2 SB41.1 TP25.1)
VDD_HV': pca10084_sheet6_connectors (P20.11 P26.11), pca10084_sheet7_power_supply (5 pins)
VDD_nRF: pca10084_sheet2_nrf52840_mcu (11 pins), pca10084_sheet6_connectors (P20.1 P26.1), pca10084_sheet7_power_supply (5 pins)
VDD_nRF': pca10084_sheet6_connectors (P20.2 P26.2 SB60.2), pca10084_sheet7_power_supply (P22.2 R90.1 SB40.2 SW9.3)
VDD_SAM: pca10084_sheet4_interface_mcu (24 pins), pca10084_sheet6_connectors (J4.1 R64.2 R65.2 R66.2), pca10084_sheet7_power_supply (SB37.1 TP35.1 U18.A1)
VDD_UTMI: pca10084_sheet4_interface_mcu (C28.2 SB49.2 U2.79), pca10084_sheet7_power_supply (SB48.1 U24.A1)
VIN3-5V: pca10084_sheet6_connectors (P20.9 P26.9), pca10084_sheet7_power_supply (D83.2)
VIO: pca10084_sheet6_connectors (9 pins), pca10084_sheet7_power_supply (SB38.1)
VLi-Ion: pca10084_sheet6_connectors (J6.2 P27.2 TP31.1), pca10084_sheet7_power_supply (D82.2 SW9.5)
ANT_SEL: pca10084_sheet3_pin_map (SB10.2), pca10084_sheet8_skyworks (R10.1)
BUCK_EN: pca10084_sheet3_pin_map (SB29.2), pca10084_sheet8_skyworks (U10.C2 U26.3)
CHL: pca10084_sheet3_pin_map (SB11.2), pca10084_sheet8_skyworks (R5.1)
CPS: pca10084_sheet3_pin_map (SB14.2), pca10084_sheet8_skyworks (R33.1)
CRX: pca10084_sheet3_pin_map (SB12.2), pca10084_sheet8_skyworks (R8.1)
CSD: pca10084_sheet3_pin_map (SB15.2), pca10084_sheet8_skyworks (R9.1)
CTX: pca10084_sheet3_pin_map (SB13.2), pca10084_sheet8_skyworks (R34.1)
D_N: pca10084_sheet2_nrf52840_mcu (U1.AD4), pca10084_sheet6_connectors (R69.1)
D_P: pca10084_sheet2_nrf52840_mcu (U1.AD6), pca10084_sheet6_connectors (R70.1)
DFSD_N: pca10084_sheet4_interface_mcu (U2.80), pca10084_sheet6_connectors (R60.1)
DFSD_P: pca10084_sheet4_interface_mcu (U2.81), pca10084_sheet6_connectors (R61.1)
DHSD_N: pca10084_sheet4_interface_mcu (U2.77), pca10084_sheet6_connectors (D61.2 J2.2 R60.2 TP10.1)
DHSD_P: pca10084_sheet4_interface_mcu (U2.76), pca10084_sheet6_connectors (D61.3 J2.3 R61.2 TP9.1)
EXT_GND_DETECT: pca10084_sheet4_interface_mcu (U2.67), pca10084_sheet6_connectors (P19.9)
EXT_RESET: pca10084_sheet4_interface_mcu (U2.68), pca10084_sheet6_connectors (P19.10)
EXT_SWDCLK: pca10084_sheet4_interface_mcu (U2.70), pca10084_sheet6_connectors (P19.4)
EXT_SWDIO: pca10084_sheet4_interface_mcu (U2.71), pca10084_sheet6_connectors (P19.2)
EXT_SWO: pca10084_sheet4_interface_mcu (U2.18), pca10084_sheet6_connectors (P19.6)
EXT_VTG: pca10084_sheet4_interface_mcu (Q3.4 R24.1), pca10084_sheet6_connectors (P19.1 SB47.2)
~{IF_OFF}: pca10084_sheet4_interface_mcu (Q2.2 Q3.2 U2.90), pca10084_sheet5_misc (6 pins), pca10084_sheet7_power_supply (U18.B2 U24.B2)
IMCU_BOOT: pca10084_sheet4_interface_mcu (SB65.1 U2.24), pca10084_sheet5_misc (SB46.2 U7.15)
IMCU_CTS: pca10084_sheet4_interface_mcu (U2.38), pca10084_sheet5_misc (TP1.1 U5.3)
IMCU_RESET: pca10084_sheet4_interface_mcu (U2.57), pca10084_sheet6_connectors (J4.10 R66.1)
IMCU_RTS: pca10084_sheet4_interface_mcu (U2.39), pca10084_sheet5_misc (TP3.1 U5.15)
IMCU_RxD: pca10084_sheet4_interface_mcu (U2.40), pca10084_sheet5_misc (TP2.1 U5.11)
IMCU_TCKS: pca10084_sheet4_interface_mcu (U2.56), pca10084_sheet6_connectors (J4.4 R65.1)
IMCU_TDIS: pca10084_sheet4_interface_mcu (U2.51), pca10084_sheet6_connectors (J4.8 R67.1)
IMCU_TDOS: pca10084_sheet4_interface_mcu (U2.54), pca10084_sheet6_connectors (J4.6)
IMCU_TMSS: pca10084_sheet4_interface_mcu (U2.55), pca10084_sheet6_connectors (J4.2 R64.1)
IMCU_TxD: pca10084_sheet4_interface_mcu (U2.41), pca10084_sheet5_misc (TP4.1 U5.7)
NetC46_1: pca10084_sheet5_misc (C46.1 R44.1), pca10084_sheet6_connectors (J5.2 TP17.1)
NetC47_2: pca10084_sheet5_misc (C47.2 R46.1), pca10084_sheet6_connectors (J5.4 TP18.1)
NetP1_3: pca10084_sheet5_misc (SB43.2 SB44.1 U7.4), pca10084_sheet6_connectors (5 pins)
NetP2_6: pca10084_sheet3_pin_map (SB17.2), pca10084_sheet6_connectors (P2.6 P8.6 P14.12 TP47.1)
NetP3_8: pca10084_sheet3_pin_map (SB26.2), pca10084_sheet6_connectors (P3.8 P9.8 P15.16)
NetP6_7: pca10084_sheet5_misc (R43.1), pca10084_sheet6_connectors (P6.7 P12.7 P17.14)
NetP6_8: pca10084_sheet5_misc (R45.1), pca10084_sheet6_connectors (P6.8 P12.8 P17.16)
NetP24_7: pca10084_sheet3_pin_map (SB23.2), pca10084_sheet6_connectors (P24.7)
NetP24_9: pca10084_sheet3_pin_map (SB21.2), pca10084_sheet6_connectors (P24.9)
NetP24_10: pca10084_sheet3_pin_map (SB22.2), pca10084_sheet6_connectors (P24.10)
NetP24_11: pca10084_sheet3_pin_map (SB24.2), pca10084_sheet6_connectors (P24.11)
NetP24_12: pca10084_sheet3_pin_map (SB25.2), pca10084_sheet6_connectors (P24.12)
NetP24_13: pca10084_sheet3_pin_map (SB20.2), pca10084_sheet6_connectors (P24.13)
NetR68_1: pca10084_sheet5_misc (U7.10), pca10084_sheet6_connectors (R68.1 SB33.2 TP19.1)
NetSB16_2: pca10084_sheet3_pin_map (SB16.2), pca10084_sheet5_misc (U8.7)
OB_RESET: pca10084_sheet4_interface_mcu (U2.27), pca10084_sheet5_misc (TP7.1 U6.7)
OB_SWDCLK: pca10084_sheet4_interface_mcu (R28.2 U2.5), pca10084_sheet5_misc (TP6.1 U6.3)
OB_SWDIO: pca10084_sheet4_interface_mcu (R29.2 U2.12), pca10084_sheet5_misc (TP5.1 U6.15)
OB_SWO: pca10084_sheet4_interface_mcu (U2.20), pca10084_sheet5_misc (TP8.1 U6.11)
P0.00: pca10084_sheet2_nrf52840_mcu (SB4.2), pca10084_sheet6_connectors (P6.1 P12.1 P17.2)
P0.01: pca10084_sheet2_nrf52840_mcu (SB3.2), pca10084_sheet6_connectors (P6.2 P12.2 P17.4)
P0.02/AIN0: pca10084_sheet2_nrf52840_mcu (U1.A12), pca10084_sheet6_connectors (P4.8 P10.8 P16.16)
P0.03/AIN1: pca10084_sheet2_nrf52840_mcu (U1.B13), pca10084_sheet6_connectors (P2.1 P8.1 P14.2 TP42.1)
P0.04/AIN2: pca10084_sheet2_nrf52840_mcu (U1.J1), pca10084_sheet5_misc (U8.15), pca10084_sheet6_connectors (P2.2 P8.2 P14.4 TP43.1)
P0.05/AIN3: pca10084_sheet2_nrf52840_mcu (U1.K2), pca10084_sheet5_misc (SB51.1), pca10084_sheet6_connectors (P6.3 P12.3 P17.6)
P0.06: pca10084_sheet2_nrf52840_mcu (U1.L1), pca10084_sheet5_misc (SB53.1), pca10084_sheet6_connectors (P6.4 P12.4 P17.8)
P0.07: pca10084_sheet2_nrf52840_mcu (U1.M2), pca10084_sheet5_misc (U8.1), pca10084_sheet6_connectors (P6.5 P12.5 P17.10 P25.12)
P0.08: pca10084_sheet2_nrf52840_mcu (U1.N1), pca10084_sheet5_misc (SB52.1), pca10084_sheet6_connectors (P6.6 P12.6 P17.12)
P0.09/NFC1: pca10084_sheet2_nrf52840_mcu (U1.L24), pca10084_sheet5_misc (R43.2 R44.2)
P0.10/NFC2: pca10084_sheet2_nrf52840_mcu (U1.J24), pca10084_sheet5_misc (R45.2 R46.2)
P0.11: pca10084_sheet2_nrf52840_mcu (U1.T2), pca10084_sheet5_misc (U8.5), pca10084_sheet6_connectors (P24.1 P25.18)
P0.12: pca10084_sheet2_nrf52840_mcu (U1.U1), pca10084_sheet5_misc (U8.9), pca10084_sheet6_connectors (P24.2 P25.16)
P0.13: pca10084_sheet2_nrf52840_mcu (U1.AD8), pca10084_sheet5_misc (SB5.1), pca10084_sheet6_connectors (P24.3)
P0.14: pca10084_sheet2_nrf52840_mcu (U1.AC9), pca10084_sheet5_misc (SB6.1), pca10084_sheet6_connectors (P24.4)
P0.15: pca10084_sheet2_nrf52840_mcu (U1.AD10), pca10084_sheet5_misc (SB7.1), pca10084_sheet6_connectors (P24.5)
P0.16: pca10084_sheet2_nrf52840_mcu (U1.AC11), pca10084_sheet5_misc (SB8.1), pca10084_sheet6_connectors (P24.6)
P0.17: pca10084_sheet2_nrf52840_mcu (U1.AD12), pca10084_sheet3_pin_map (SB13.1 SB23.1)
P0.18/RESET: pca10084_sheet2_nrf52840_mcu (U1.AC13), pca10084_sheet5_misc (SB42.2 SB44.2 SB45.2 SB56.1), pca10084_sheet6_connectors (P18.10 P24.8 P25.10)
P0.19: pca10084_sheet2_nrf52840_mcu (U1.AC15), pca10084_sheet3_pin_map (SB11.1 SB21.1)
P0.20: pca10084_sheet2_nrf52840_mcu (U1.AD16), pca10084_sheet3_pin_map (SB12.1 SB22.1)
P0.21: pca10084_sheet2_nrf52840_mcu (U1.AC17), pca10084_sheet3_pin_map (SB14.1 SB24.1)
P0.22: pca10084_sheet2_nrf52840_mcu (U1.AD18), pca10084_sheet3_pin_map (SB15.1 SB25.1)
P0.23: pca10084_sheet2_nrf52840_mcu (U1.AC19), pca10084_sheet3_pin_map (SB10.1 SB20.1)
P0.24: pca10084_sheet2_nrf52840_mcu (U1.AD20), pca10084_sheet5_misc (SW3.2), pca10084_sheet6_connectors (P24.14)
P0.25: pca10084_sheet2_nrf52840_mcu (U1.AC21), pca10084_sheet5_misc (SW4.2), pca10084_sheet6_connectors (P24.15)
P0.26: pca10084_sheet2_nrf52840_mcu (U1.G1), pca10084_sheet3_pin_map (C51.2 R1.2)
P0.27: pca10084_sheet2_nrf52840_mcu (U1.H2), pca10084_sheet3_pin_map (C52.1 R2.2)
P0.28/AIN4: pca10084_sheet2_nrf52840_mcu (U1.B11), pca10084_sheet6_connectors (P2.3 P8.3 P14.6 TP44.1)
P0.29/AIN5: pca10084_sheet2_nrf52840_mcu (U1.A10), pca10084_sheet6_connectors (P2.4 P8.4 P14.8 TP45.1)
P0.30/AIN6: pca10084_sheet2_nrf52840_mcu (U1.B9), pca10084_sheet6_connectors (P2.5 P8.5 P14.10 TP46.1)
P0.31/AIN7: pca10084_sheet2_nrf52840_mcu (U1.A8), pca10084_sheet3_pin_map (SB17.1 SB29.1)
P1.00: pca10084_sheet2_nrf52840_mcu (U1.AD22), pca10084_sheet5_misc (SB57.1), pca10084_sheet6_connectors (P18.6 P24.16 P25.6 P25.14)
P1.01: pca10084_sheet2_nrf52840_mcu (U1.Y23), pca10084_sheet6_connectors (P3.1 P9.1 P15.2)
P1.02: pca10084_sheet2_nrf52840_mcu (U1.W24), pca10084_sheet6_connectors (P3.2 P9.2 P15.4)
P1.03: pca10084_sheet2_nrf52840_mcu (U1.V23), pca10084_sheet6_connectors (P3.3 P9.3 P15.6)
P1.04: pca10084_sheet2_nrf52840_mcu (U1.U24), pca10084_sheet6_connectors (P3.4 P9.4 P15.8)
P1.05: pca10084_sheet2_nrf52840_mcu (U1.T23), pca10084_sheet6_connectors (P3.5 P9.5 P15.10)
P1.06: pca10084_sheet2_nrf52840_mcu (U1.R24), pca10084_sheet6_connectors (P3.6 P9.6 P15.12)
P1.07: pca10084_sheet2_nrf52840_mcu (U1.P23), pca10084_sheet5_misc (U8.3), pca10084_sheet6_connectors (P3.7 P9.7 P15.14)
P1.08: pca10084_sheet2_nrf52840_mcu (U1.P2), pca10084_sheet3_pin_map (SB16.1 SB26.1 SB61.1)
P1.09: pca10084_sheet2_nrf52840_mcu (U1.R1), pca10084_sheet6_connectors (P24.17 P25.20)
P1.10: pca10084_sheet2_nrf52840_mcu (U1.A20), pca10084_sheet6_connectors (P4.1 P10.1 P16.2)
P1.11: pca10084_sheet2_nrf52840_mcu (U1.B19), pca10084_sheet6_connectors (P4.2 P10.2 P16.4)
P1.12: pca10084_sheet2_nrf52840_mcu (U1.B17), pca10084_sheet6_connectors (P4.3 P10.3 P16.6)
P1.13: pca10084_sheet2_nrf52840_mcu (U1.A16), pca10084_sheet6_connectors (5 pins)
P1.14: pca10084_sheet2_nrf52840_mcu (U1.B15), pca10084_sheet6_connectors (5 pins)
P1.15: pca10084_sheet2_nrf52840_mcu (U1.A14), pca10084_sheet6_connectors (5 pins)
PWM_IN: pca10084_sheet3_pin_map (SB61.2), pca10084_sheet8_skyworks (R11.1)
RF: pca10084_sheet2_nrf52840_mcu (C4.2 C22.1 L1.2), pca10084_sheet8_skyworks (U9.21)
SCL: pca10084_sheet3_pin_map (R2.1), pca10084_sheet5_misc (U7.12), pca10084_sheet6_connectors (P4.10 P10.10 P16.20), pca10084_sheet8_skyworks (U10.D1)
SDA: pca10084_sheet3_pin_map (R1.1), pca10084_sheet5_misc (U7.8), pca10084_sheet6_connectors (P4.9 P10.9 P16.18), pca10084_sheet8_skyworks (U10.D2)
SH_GND_DETECT: pca10084_sheet4_interface_mcu (U2.62), pca10084_sheet6_connectors (P20.8 P26.8)
SH_RESET: pca10084_sheet4_interface_mcu (U2.63), pca10084_sheet6_connectors (P20.7 P26.7)
SH_SWDCLK: pca10084_sheet4_interface_mcu (U2.65), pca10084_sheet6_connectors (P20.5 P26.5)
SH_SWDIO: pca10084_sheet4_interface_mcu (U2.66), pca10084_sheet6_connectors (P20.4 P26.4)
SH_SWO: pca10084_sheet4_interface_mcu (U2.21), pca10084_sheet6_connectors (P20.6 P26.6)
SH_VTG: pca10084_sheet4_interface_mcu (Q2.4 R22.1), pca10084_sheet6_connectors (P20.3 P26.3)
SWDCLK: pca10084_sheet2_nrf52840_mcu (U1.AA24), pca10084_sheet5_misc (SB55.1), pca10084_sheet6_connectors (P18.4 P25.4)
SWDIO: pca10084_sheet2_nrf52840_mcu (U1.AC24), pca10084_sheet5_misc (SB54.1), pca10084_sheet6_connectors (P18.2 P25.2)

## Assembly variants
Buck: not fitted C95 C96 L5 U10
